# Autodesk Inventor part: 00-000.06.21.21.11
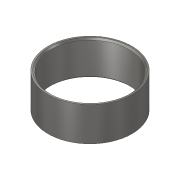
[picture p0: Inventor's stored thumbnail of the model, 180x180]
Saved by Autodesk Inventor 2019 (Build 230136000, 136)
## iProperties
Created: 2019-01
Part Number: 00-000.06.21.21.11
Material: Steel, Mild
Document SubType Name: Modeling
Designer: m.vorobev
Density: 7.85 g/cm^3
Appearance: Semi-Polished
Author: m.vorobev
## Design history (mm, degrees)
derived "00-000.06.21.21.11,12,13.ipt"
feature "Solid1::00-000.06.21.21.11,12,13.ipt"
tag "TaggingFeature1"
body "Solid1"
other parameters: "D1" = 86, "B" = 35, "d4" = 1.5
